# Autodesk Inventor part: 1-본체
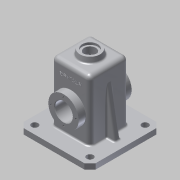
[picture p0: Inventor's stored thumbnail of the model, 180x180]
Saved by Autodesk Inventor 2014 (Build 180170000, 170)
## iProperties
Created: 2016-02
Part Number: 1-본체
Material: 알루미늄 6061
Document SubType Name: Modeling
Designer: 406-05
Density: 2.71 g/cm^3
Appearance: 알루미늄 - 평지
Mass: 932.813 g
Surface Area: 1043.48 cm^2
Volume: 344.211 cm^3
Author: 406-05
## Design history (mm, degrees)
sketch "스케치1"
  geometry: L1 (-35, 35)-(35, 35); L2 (35, 35)-(35, -35); L3 (35, -35)-(-35, -35); L4 (-35, -35)-(-35, 35); L5 (-35, 35)-(35, -35); L6 (35, 35)-(-35, -35); 1 further point
  constraints: 12 end point, 2 midpoint, 2 parallel, 1 horizontal, 1 perpendicular
  dimensions: "d0" = 70 distance of L1.start L1.end; "d1" = 70 distance of L1.end L2.end
extrude "돌출1" new body sketch "스케치1" distance "d2" = 120; taper "d3" = 0 deg
sketch "스케치2"
  geometry: L1 (-65, 65)-(65, 65); L2 (65, 65)-(65, -65); L3 (65, -65)-(-65, -65); L4 (-65, -65)-(-65, 65); L5 (-65, 65)-(65, -65); L6 (65, 65)-(-65, -65); 1 further point
  constraints: 12 end point, 2 midpoint, 2 parallel, 1 horizontal, 1 perpendicular
  dimensions: "d4" = 130 distance of L1.start L1.end; "d5" = 130 distance of L1.end L2.end
extrude "돌출2" join sketch "스케치2" distance "d6" = 10; taper "d7" = 0 deg
chamfer "모따기1" distance "d8" = 10; stored, may be unused: second distance "d9" = 2, angle "d10" = 45 deg
sketch "스케치3"
  geometry: L1 (55, 65)-(-55, 65) reference; L2 (-50, 50)-(50, 50); L3 (50, 50)-(50, -50); L4 (50, -50)-(-50, -50); L5 (-50, -50)-(-50, 50); L6 (-50, 50)-(50, -50); L7 (50, 50)-(-50, -50); 5 further points
  constraints: 12 end point, 4 coincident, 2 midpoint, 2 parallel, 1 horizontal, 1 perpendicular
  dimensions: "d12" = 100 distance of L2.start L2.end; "d13" = 100 distance of L2.end L3.end
hole "구멍1" sketch "스케치3" at (-50, 50), (-50, -50), (50, -50), (50, 50) diameter "d14" = 12; stored, may be unused: countersink angle "d18" = 90 deg, drill point angle "d20" = 118 deg; dims "d15" = 6, "d16" = 4, "d17" = 2, "d19" = 8
fillet "모깎기1" dims "d22" = 8
fillet "모깎기2" dims "d23" = 8
sketch "스케치4"
  geometry: C1 r 27.5 at (0, 55); 1 further point
  constraints: 1 centre point
  dimensions: "d24" = 55 diameter of C1; "d25" = 55 distance of point (0, 0) C1.centre
extrude "돌출3" join sketch "스케치4" stored distance "d26" = 96; taper "d27" = 0 deg
sketch "스케치5"
  geometry: C1 r 20 at (0, 0); 1 further point
  constraints: 1 centre point, 1 coincident
  dimensions: "d28" = 40 diameter of C1
extrude "돌출4" join sketch "스케치5" distance "d29" = 10; taper "d30" = -10 deg; dims "d20" = 118 deg
node "작업 평면1"
sketch "스케치6"
  geometry: L1 (27, 35)-(-27, 35) reference; L2 (-35, 27)-(-35, -27) reference; L3 (35, -27)-(35, 27) reference; L4 (-27, -35)-(27, -35) reference; L5 (27, 30)-(-27, 30); L6 (-30, 27)-(-30, -27); L7 (-27, -30)-(27, -30); L8 (30, -27)-(30, 27); A1 r 8 centre (-27, 27) between (-27, 35) and (-35, 27) reference; A2 r 8 centre (27, 27) between (35, 27) and (27, 35) reference; A3 r 8 centre (27, -27) between (27, -35) and (35, -27) reference; A4 r 8 centre (-27, -27) between (-35, -27) and (-27, -35) reference; A5 r 3 centre (27, 27) between (30, 27) and (27, 30); A6 r 3 centre (-27, 27) between (-27, 30) and (-30, 27); A7 r 3 centre (-27, -27) between (-30, -27) and (-27, -30); A8 r 3 centre (27, -27) between (27, -30) and (30, -27); 1 further point
  constraints: 8 end point, 8 point on circle, 4 centre point, 7 other
  dimensions: "d32" = 5 distance between parallel lines of L3 L8
extrude "돌출5" cut sketch "스케치6" stored distance "d33" = 10; taper "d34" = 0 deg
sketch "스케치8"
  geometry: C1 r 27.5 at (27, 60); 1 further point
  constraints: 1 centre point
  dimensions: "d47" = 55 diameter of C1; "d48" = 55 distance of point (27, 115) C1.centre
extrude "돌출7" join sketch "스케치8" distance "d49" = 7; taper "d50" = -45 deg
hole "구멍3" diameter "d53" = 32; stored, may be unused: countersink angle "d57" = 90 deg, drill point angle "d59" = 118 deg; dims "d51" = 10, "d52" = 10, "d54" = 6, "d55" = 4, "d56" = 2, "d58" = 8
hole "구멍4" diameter "d62" = 21; stored, may be unused: countersink angle "d66" = 90 deg, drill point angle "d68" = 118 deg; dims "d60" = 10, "d61" = 10, "d63" = 6, "d64" = 28, "d65" = 4, "d67" = 8
sketch "스케치9"
  geometry: C1 r 16 at (0, 0) reference; 2 further points
  constraints: 1 vertical alignment
  dimensions: "d69" = 22.5 distance of C1.centre point (0, 22.5)
hole "구멍5" sketch "스케치9" at (0, 22.5) diameter "d70" = 3.242; stored, may be unused: countersink angle "d74" = 90 deg, drill point angle "d76" = 118 deg; dims "d71" = 8, "d72" = 28, "d73" = 4, "d75" = 10
fillet "모깎기3" dims "d80" = 3
sketch "스케치10"
  geometry: L1 (50, 10)-(35, 95.069); L2 (35, 112)-(35, 10) reference; L3 (44, 10)-(56, 10) reference; L4 (55, 10)-(65, 10) reference; L5 (65, 10)-(65, 0) reference; 1 further point
  constraints: 2 end point, 2 point on line
  dimensions: "d81" = 15 distance from line of L5 L1.start; "d100" = 10 deg angle of L5 L1
feature "리브1" sketch "스케치10" dims "d82" = 1, "d83" = 10, "d84" = 0, "d85" = 0, "d86" = 1, "d87" = 1
sketch "스케치11"
  geometry: L1 (8.763, 18)-(45.237, 18) reference; A1 r 27.5 centre (27, -57) between (54, -51.78) and (0, -51.78) reference; 2 further points
  constraints: 1 vertical alignment, 1 other
  dimensions: "d88" = 30 distance from line of point (27, -12) L1
feature "엠보싱1" sketch "스케치11" dims "d0" = 70, "d1" = 70, "d89" = 0.5, "d90" = 0
fillet "모깎기4" dims "d91" = 0.5
chamfer "모따기2" distance "d92" = 1; stored, may be unused: second distance "d93" = 2, angle "d94" = 45 deg
fillet "모깎기5" dims "d95" = 3
fillet "모깎기6" dims "d96" = 3
fillet "모깎기7" dims "d97" = 3
fillet "모깎기8" dims "d98" = 0.5
fillet "모깎기9" dims "d99" = 3
node "솔리드1"
mirror "대칭2"
pattern_circular "원형 패턴1" dims angle "d78" = 360 deg
mirror "대칭3"
mirror "대칭4"
other parameters: "d31" = -5
